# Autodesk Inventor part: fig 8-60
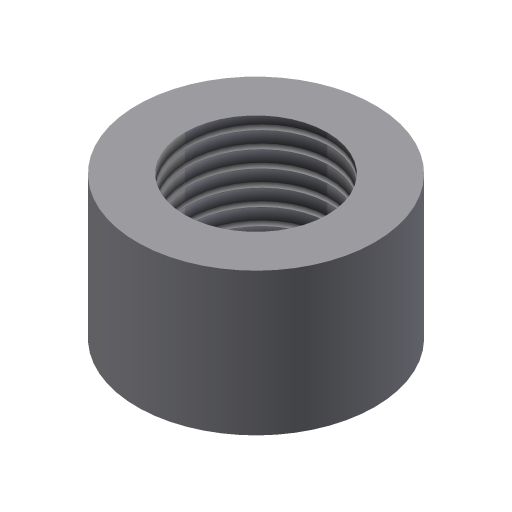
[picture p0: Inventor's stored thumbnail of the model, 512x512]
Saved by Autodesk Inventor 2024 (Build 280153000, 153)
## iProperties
Shininess: 77.0
Length Units: 11269
Angle Units: 11279
Time Units: 11290
Mass Units: 11283
Length Display Precision: 3
Angle Display Precision: 2
Compacted: True
Created: 2002-01
Part Number: fig 8-60
Document SubType Name: Modeling
Designer: ***
Density: 1 g/cm^3
Material: Generic
Appearance: Default
Density: 0.0
Volumn: 0.0
Area: 0.0
PropertySet Name: Model Information
Control State: 0
Master: False
Checked Out: False
Author: ***
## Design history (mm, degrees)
sketch "Sketch1"
  geometry: C1 r 25 at (0, 0); C2 r 15 at (0, 0)
  constraints: 2 centre point, 1 coincident
  dimensions: "d0" = 50 diameter of C1; "d1" = 30 diameter of C2
extrude "Extrusion1" new body sketch "Sketch1" distance "d2" = 30; taper "d3" = 0 deg
thread "Thread5" dims "d12" = 10, "d13" = 0
body "Solid1"
